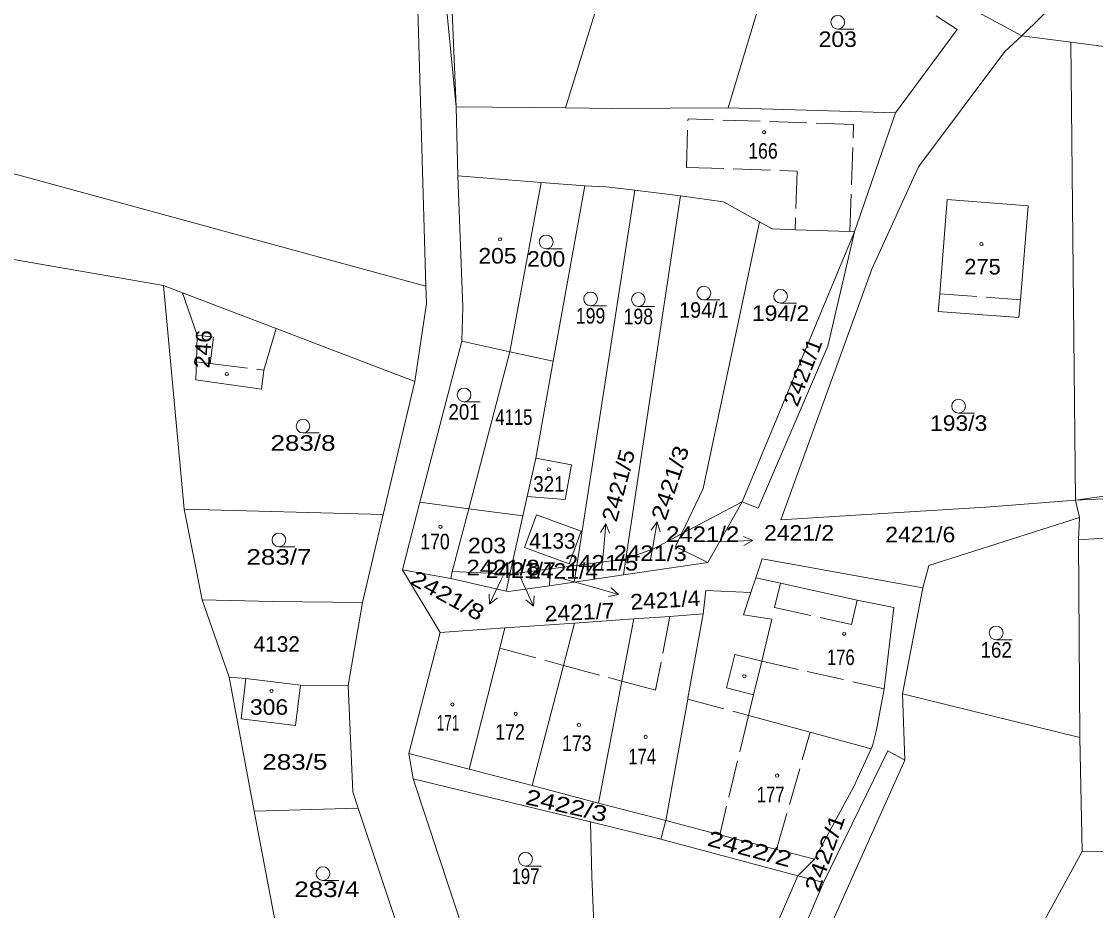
# Model space of a CAD drawing. Extents: x -590528 to -586543, y -1119609 to -1116685.
# Drawn here: x -589035.6 to -588918.3, y -1118218.9 to -1118121.8 of the extents above; entities that cross this region are included whole.
import ezdxf
from ezdxf.enums import TextEntityAlignment as Align

# ---------------------------------------------------------------- set-up
doc = ezdxf.new("R2010")
doc.units = 0
doc.header["$LTSCALE"] = 0.68
doc.linetypes.add('LONG_DASHED', pattern=[7.5, 6, -1.5])
for name, color, linetype, lineweight in [('1', 7, 'Continuous', 13), ('2', 7, 'LONG_DASHED', 13), ('3', 7, 'Continuous', 13), ('6', 7, 'Continuous', 13)]:
    doc.layers.add(name, color=color, linetype=linetype, lineweight=lineweight)

msp = doc.modelspace()

# ---------------------------------------------------------------- linework, layer by layer
at = {"layer": '1'}
for p, q in [((-588993.92, -1118065.79), (-588991.42, -1118150.69)), ((-588958.38, -1118131.22), (-588951.97, -1118109.75)), ((-588970.83, -1118113.91), (-588976.15, -1118131.23)), ((-588921.38, -1118118.49), (-588926.3, -1118123.37)), ((-588991.42, -1118150.69), (-589107.54, -1118119.06)), ((-588934.5, -1118118.92), (-588926.3, -1118123.37)), ((-588935.65, -1118121.17), (-588933.39, -1118122.65)), ((-588940.12, -1118131.78), (-588933.39, -1118122.65)), ((-588902.6, -1118126.42), (-588920.96, -1118124.06)), ((-588988.11, -1118131.1), (-588987.93, -1118138.66)), ((-588958.38, -1118131.22), (-588971.08, -1118131.29)), ((-588940.12, -1118131.78), (-588958.38, -1118131.22)), ((-588944.59, -1118144.75), (-588940.12, -1118131.78)), ((-588978.84, -1118139.38), (-588987.93, -1118138.66)), ((-588987.93, -1118138.66), (-588987.39, -1118153.01)), ((-588982.25, -1118157.86), (-588978.84, -1118139.38)), ((-588968.59, -1118140.23), (-588974.94, -1118181.22)), ((-588963.6, -1118140.83), (-588969.57, -1118180.5)), ((-588926.45, -1118152.2), (-588925.63, -1118141.93)), ((-588954.98, -1118143.67), (-588961.12, -1118172.82)), ((-588944.59, -1118144.75), (-588956.86, -1118174.25)), ((-588953.58, -1118144.44), (-588951.09, -1118144.53)), ((-588951.09, -1118144.53), (-588945.09, -1118144.73)), ((-588944.59, -1118144.75), (-588947.52, -1118157.25)), ((-588945.09, -1118144.73), (-588944.59, -1118144.75)), ((-589020.1, -1118150.63), (-589017.84, -1118175.07)), ((-588991.42, -1118150.69), (-588991.36, -1118152.59)), ((-589016.4, -1118156.04), (-589018.03, -1118151.42)), ((-588926.45, -1118152.2), (-588926.63, -1118154.13)), ((-588991.36, -1118152.59), (-588992.63, -1118161.11)), ((-588987.39, -1118153.01), (-588987.5, -1118156.69)), ((-589009.12, -1118159.87), (-589007.77, -1118155.33)), ((-588992.63, -1118161.11), (-589007.77, -1118155.33)), ((-588987.5, -1118156.69), (-588992.09, -1118174.29)), ((-588987.5, -1118156.69), (-588982.25, -1118157.86)), ((-588947.52, -1118157.25), (-588955.11, -1118174.96)), ((-588982.25, -1118157.86), (-588977.51, -1118158.9)), ((-589009.38, -1118161.96), (-589009.12, -1118159.87)), ((-589016.56, -1118160.95), (-589009.38, -1118161.96)), ((-588996.08, -1118175.63), (-588992.63, -1118161.11)), ((-588979.41, -1118169.5), (-588975.51, -1118170.21)), ((-588975.51, -1118170.21), (-588976.2, -1118174.01)), ((-588980.34, -1118173.66), (-588976.2, -1118174.01)), ((-588961.12, -1118172.82), (-588963.48, -1118177.76)), ((-588919.99, -1118175.98), (-588920.43, -1118174.06)), ((-589017.84, -1118175.07), (-588996.08, -1118175.63)), ((-589017.84, -1118175.07), (-589015.85, -1118184.98)), ((-588998.36, -1118185.26), (-588996.08, -1118175.63)), ((-588980.82, -1118175.8), (-588982.24, -1118182.15)), ((-588979.35, -1118175.67), (-588980.66, -1118179.24)), ((-588974.47, -1118177.46), (-588979.35, -1118175.67)), ((-588936.45, -1118181.22), (-588919.99, -1118175.98)), ((-588889.64, -1118176.31), (-588920.1, -1118178.41)), ((-588974.47, -1118177.46), (-588975.78, -1118181.03)), ((-588963.48, -1118177.76), (-588964.14, -1118179.15)), ((-588980.66, -1118179.24), (-588975.78, -1118181.03)), ((-588966.54, -1118179.39), (-588969.57, -1118180.5)), ((-588964.14, -1118179.15), (-588960.63, -1118180.9)), ((-588969.57, -1118180.5), (-588974.94, -1118181.22)), ((-588969.57, -1118180.5), (-588969.83, -1118182.24)), ((-588937.13, -1118183.65), (-588954.68, -1118180.5)), ((-588993.99, -1118181.68), (-588989.86, -1118188.53)), ((-588982.24, -1118182.15), (-588988.54, -1118181.86)), ((-588977.83, -1118181.59), (-588982.24, -1118182.15)), ((-588977.83, -1118181.59), (-588977.92, -1118183.42)), ((-588974.94, -1118181.22), (-588977.83, -1118181.59)), ((-588960.63, -1118180.9), (-588969.83, -1118182.24)), ((-588982.24, -1118182.15), (-588982.66, -1118184.01)), ((-588969.83, -1118182.24), (-588975.22, -1118183.03)), ((-588952.69, -1118183.15), (-588955.37, -1118182.56)), ((-588977.92, -1118183.42), (-588982.38, -1118184.07)), ((-588944.31, -1118184.99), (-588952.69, -1118183.15)), ((-589015.85, -1118184.98), (-589008.19, -1118185.14)), ((-589012.92, -1118193.43), (-589015.85, -1118184.98)), ((-589008.19, -1118185.14), (-588998.36, -1118185.26)), ((-588999.9, -1118194.31), (-588998.36, -1118185.26)), ((-588940.28, -1118185.8), (-588944.31, -1118184.99)), ((-588961.13, -1118186.48), (-588964.76, -1118186.77)), ((-588962.79, -1118195.7), (-588961.13, -1118186.48)), ((-588953.63, -1118187.08), (-588956.71, -1118186.59)), ((-588941.34, -1118194.68), (-588940.28, -1118185.8)), ((-588975.17, -1118187.5), (-588976.38, -1118192.12)), ((-588968.69, -1118187.05), (-588970.01, -1118193.85)), ((-588964.76, -1118186.77), (-588968.69, -1118187.05)), ((-588954.73, -1118191.66), (-588953.63, -1118187.08)), ((-588982.79, -1118188.03), (-588989.86, -1118188.53)), ((-588982.79, -1118188.03), (-588983.35, -1118190.23)), ((-588957.67, -1118190.93), (-588954.73, -1118191.66)), ((-588976.38, -1118192.12), (-588979.82, -1118205.26)), ((-589011.08, -1118193.54), (-589012.92, -1118193.43)), ((-589011.08, -1118193.54), (-589011.62, -1118197.97)), ((-589011.08, -1118193.54), (-589005.12, -1118194.27)), ((-589005.12, -1118194.27), (-589005.66, -1118198.7)), ((-589005.12, -1118194.27), (-588999.9, -1118194.31)), ((-588999.42, -1118205.92), (-588999.9, -1118194.31)), ((-588970.01, -1118193.85), (-588972.57, -1118207.16)), ((-588942.18, -1118199.18), (-588941.34, -1118194.68)), ((-588919.98, -1118200.01), (-588939.36, -1118195.25)), ((-589011.62, -1118197.97), (-589005.66, -1118198.7)), ((-588949.42, -1118199.43), (-588942.77, -1118201.23)), ((-588942.63, -1118200.92), (-588942.18, -1118199.18)), ((-588919.98, -1118200.01), (-588919.7, -1118212.47)), ((-588993.28, -1118201.74), (-588986.71, -1118203.46)), ((-588964.17, -1118258.31), (-588939.08, -1118202.48)), ((-588992.82, -1118204.5), (-588986.92, -1118222.32)), ((-588948.96, -1118213.3), (-588944.68, -1118205.37)), ((-588998.82, -1118207.72), (-588999.42, -1118205.92)), ((-589010.17, -1118208.04), (-588998.82, -1118207.72)), ((-588972.57, -1118207.16), (-588965.2, -1118209.08)), ((-588973.28, -1118215.23), (-588973.44, -1118209.23)), ((-588965.75, -1118211.1), (-588965.2, -1118209.08)), ((-588965.2, -1118209.08), (-588959.31, -1118210.62)), ((-588965.75, -1118211.1), (-588950.77, -1118215.1)), ((-588957.24, -1118211.17), (-588959.31, -1118210.62)), ((-588952.06, -1118212.5), (-588948.96, -1118213.3)), ((-588948.96, -1118213.3), (-588950.77, -1118215.1)), ((-588919.7, -1118212.47), (-588948.76, -1118265.18)), ((-588973.03, -1118221.16), (-588973.28, -1118215.23)), ((-588967.71, -1118253.93), (-588950.77, -1118215.1)), ((-588947.96, -1118215.85), (-588965.82, -1118257.59)), ((-588950.77, -1118215.1), (-588947.96, -1118215.85))]:
    msp.add_line(p, q, dxfattribs=at)
for points in [[(-588992.07, -1118090.31), (-588988.11, -1118131.1), (-588989.35, -1118101.59)], [(-589136.75, -1118118.6), (-589071.59, -1118141.72), (-589020.1, -1118150.63)], [(-588920.96, -1118124.06), (-588920.43, -1118174.06), (-588930.25, -1118174.85), (-588943.89, -1118175.68)], [(-588920.96, -1118124.06), (-588926.3, -1118123.37), (-588928.17, -1118125.08), (-588937.6, -1118137.68), (-588942.7, -1118148.83)], [(-588971.08, -1118131.29), (-588976.15, -1118131.23), (-588988.11, -1118131.1)], [(-588971.74, -1118139.85), (-588974.07, -1118139.74), (-588978.84, -1118139.38)], [(-588979.41, -1118169.5), (-588977.51, -1118158.9), (-588974.07, -1118139.74)], [(-588958.9, -1118141.49), (-588963.6, -1118140.83), (-588968.59, -1118140.23), (-588971.74, -1118139.85)], [(-588953.58, -1118144.44), (-588954.98, -1118143.67), (-588958.9, -1118141.49)], [(-588925.63, -1118141.93), (-588934.46, -1118141.24), (-588935.28, -1118151.52)], [(-588942.7, -1118148.83), (-588952.65, -1118176.23), (-588943.89, -1118175.68)], [(-589007.77, -1118155.33), (-589018.03, -1118151.42), (-589020.1, -1118150.63)], [(-588935.28, -1118151.52), (-588935.43, -1118153.45), (-588926.63, -1118154.13)], [(-589016.56, -1118160.95), (-589016.5, -1118158.95), (-589016.4, -1118156.04)], [(-588988.68, -1118182.63), (-588988.54, -1118181.86), (-588986.74, -1118175.01), (-588982.25, -1118157.86)], [(-588980.82, -1118175.8), (-588980.34, -1118173.66), (-588979.41, -1118169.5)], [(-588920.43, -1118174.06), (-588912.66, -1118173), (-588884.62, -1118169.19)], [(-588920.43, -1118174.06), (-588912.87, -1118173.7), (-588910.29, -1118173.25)], [(-588988.68, -1118182.63), (-588993.99, -1118181.68), (-588992.09, -1118174.29)], [(-588992.09, -1118174.29), (-588986.74, -1118175.01), (-588980.82, -1118175.8)], [(-588966.54, -1118179.39), (-588963.48, -1118177.76), (-588956.86, -1118174.25)], [(-588955.11, -1118174.96), (-588956.86, -1118174.25), (-588960.63, -1118180.9)], [(-588919.98, -1118200.01), (-588920.1, -1118178.41), (-588919.99, -1118175.98)], [(-588954.68, -1118180.5), (-588955.37, -1118182.56), (-588955.91, -1118184.18), (-588956.71, -1118186.59)], [(-588974.94, -1118181.22), (-588975.22, -1118183.03), (-588977.92, -1118183.42)], [(-588939.36, -1118195.25), (-588937.13, -1118183.65), (-588936.45, -1118181.22)], [(-588982.38, -1118184.07), (-588982.66, -1118184.01), (-588988.68, -1118182.63)], [(-588961.13, -1118186.48), (-588960.83, -1118183.95), (-588955.91, -1118184.18)], [(-588968.69, -1118187.05), (-588975.17, -1118187.5), (-588982.79, -1118188.03)], [(-588989.86, -1118188.53), (-588993.28, -1118201.74), (-588992.82, -1118204.5)], [(-588983.35, -1118190.23), (-588986.71, -1118203.46), (-588979.82, -1118205.26), (-588972.57, -1118207.16)], [(-588955.62, -1118195.35), (-588958.57, -1118194.57), (-588957.67, -1118190.93)], [(-589007.39, -1118222.8), (-589010.17, -1118208.04), (-589012.92, -1118193.43)], [(-588965.2, -1118209.08), (-588962.81, -1118195.8), (-588962.79, -1118195.7)], [(-588955.62, -1118195.35), (-588956.16, -1118197.6), (-588949.42, -1118199.43)], [(-588947.96, -1118215.85), (-588940.96, -1118201.47), (-588939.08, -1118202.48), (-588939.36, -1118195.25)], [(-588944.68, -1118205.37), (-588942.77, -1118201.23), (-588942.63, -1118200.92)], [(-588992.82, -1118204.5), (-588973.44, -1118209.23), (-588965.75, -1118211.1)], [(-588991.47, -1118229.81), (-588994.05, -1118222.05), (-588998.82, -1118207.72)], [(-588957.24, -1118211.17), (-588953.13, -1118212.23), (-588952.06, -1118212.5)], [(-588919.7, -1118212.47), (-588910.11, -1118212.57), (-588900.28, -1118212.67)]]:
    msp.add_lwpolyline(points, dxfattribs=at)
at = {"layer": '2'}
for p, q in [((-588962.96, -1118137.72), (-588962.78, -1118132.42)), ((-588944.69, -1118133.04), (-588962.78, -1118132.42)), ((-588945.09, -1118144.73), (-588944.69, -1118133.04)), ((-588962.96, -1118137.72), (-588950.87, -1118138.13)), ((-588950.87, -1118138.13), (-588951.09, -1118144.53)), ((-588935.28, -1118151.52), (-588926.45, -1118152.2)), ((-589016.4, -1118156.04), (-589014.62, -1118156.26)), ((-589014.62, -1118156.26), (-589014.98, -1118159.14)), ((-589016.5, -1118158.95), (-589014.98, -1118159.14)), ((-589014.98, -1118159.14), (-589009.12, -1118159.87)), ((-588953.33, -1118185.81), (-588952.69, -1118183.15)), ((-588944.31, -1118184.99), (-588944.9, -1118187.66)), ((-588953.33, -1118185.81), (-588944.9, -1118187.66)), ((-588964.76, -1118186.77), (-588966.33, -1118194.85)), ((-588954.73, -1118191.66), (-588955.62, -1118195.35)), ((-588954.73, -1118191.66), (-588941.34, -1118194.68)), ((-588970.01, -1118193.85), (-588966.33, -1118194.85)), ((-588962.81, -1118195.8), (-588956.16, -1118197.6)), ((-588956.16, -1118197.6), (-588959.31, -1118210.62)), ((-588953.13, -1118212.23), (-588949.42, -1118199.43))]:
    msp.add_line(p, q, dxfattribs=at)
msp.add_lwpolyline([(-588983.35, -1118190.23), (-588976.38, -1118192.12), (-588970.01, -1118193.85)], dxfattribs=at)
at = {"layer": '3'}
for p, q in [((-588971.748, -1118176.653), (-588972.03, -1118179.64)), ((-588966.141, -1118176.447), (-588966.67, -1118179.4)), ((-588966.91, -1118180.72), (-588966.67, -1118179.4)), ((-588961.18, -1118178.64), (-588958.71, -1118178.58)), ((-588955.711, -1118178.5), (-588958.71, -1118178.58)), ((-588972.23, -1118181.77), (-588972.03, -1118179.64)), ((-588984.469, -1118185.449), (-588983.2, -1118182.73)), ((-588982.99, -1118182.29), (-588983.2, -1118182.73)), ((-588981.05, -1118182.57), (-588980.89, -1118182.93)), ((-588979.649, -1118185.661), (-588980.89, -1118182.93)), ((-588976.43, -1118182.66), (-588973.26, -1118183.56)), ((-588970.372, -1118184.373), (-588973.26, -1118183.56))]:
    msp.add_line(p, q, dxfattribs=at)
for points in [[(-588972.339, -1118177.601), (-588971.748, -1118176.653), (-588971.343, -1118177.696)], [(-588966.809, -1118177.343), (-588966.141, -1118176.447), (-588965.824, -1118177.52)], [(-588956.723, -1118178.028), (-588955.711, -1118178.5), (-588956.698, -1118179.028)], [(-588971.199, -1118183.622), (-588970.372, -1118184.373), (-588971.471, -1118184.584)], [(-588983.594, -1118184.754), (-588984.469, -1118185.449), (-588984.5, -1118184.33)], [(-588979.608, -1118184.545), (-588979.649, -1118185.661), (-588980.519, -1118184.958)]]:
    msp.add_lwpolyline(points, dxfattribs=at)
at = {"layer": '6'}
for p, q in [((-588946.42, -1118122.62), (-588944.67, -1118122.62)), ((-588978.28, -1118146.62), (-588976.53, -1118146.62)), ((-588961.05, -1118152.2), (-588959.3, -1118152.2)), ((-588952.67, -1118152.55), (-588950.92, -1118152.55)), ((-588973.43, -1118152.84), (-588971.68, -1118152.84)), ((-588968.21, -1118152.91), (-588966.46, -1118152.91)), ((-588987.25, -1118163.33), (-588985.5, -1118163.33)), ((-588933.21, -1118164.56), (-588931.46, -1118164.56)), ((-589004.85, -1118166.73), (-589003.1, -1118166.73)), ((-589007.48, -1118179.17), (-589005.73, -1118179.17)), ((-588929.11, -1118189.33), (-588927.36, -1118189.33)), ((-588980.54, -1118214.06), (-588978.79, -1118214.06)), ((-589002.67, -1118215.62), (-589000.92, -1118215.62))]:
    msp.add_line(p, q, dxfattribs=at)
for centre, radius in [((-588946.42, -1118121.87), 0.75), ((-588954.4702, -1118133.8804), 0.175), ((-588983.3102, -1118145.5804), 0.175), ((-588978.28, -1118145.87), 0.75), ((-588930.7202, -1118146.1004), 0.175), ((-588973.43, -1118152.09), 0.75), ((-588961.05, -1118151.45), 0.75), ((-588952.67, -1118151.8), 0.75), ((-588968.21, -1118152.16), 0.75), ((-589016.2101, -1118157.5502), 0.1172), ((-589013.1702, -1118160.3004), 0.175), ((-588987.25, -1118162.58), 0.75), ((-588933.21, -1118163.81), 0.75), ((-589004.85, -1118165.98), 0.75), ((-588977.9802, -1118170.7104), 0.175), ((-588989.8302, -1118176.9804), 0.175), ((-589007.48, -1118178.42), 0.75), ((-588945.7202, -1118188.6704), 0.175), ((-588929.11, -1118188.58), 0.75), ((-588956.6202, -1118193.3204), 0.175), ((-589008.2902, -1118194.9204), 0.175), ((-588988.5302, -1118196.4004), 0.175), ((-588981.6102, -1118197.4104), 0.175), ((-588974.7002, -1118198.6304), 0.175), ((-588967.4102, -1118199.9404), 0.175), ((-588953.0502, -1118204.1604), 0.175), ((-588980.54, -1118213.31), 0.75), ((-589002.67, -1118214.87), 0.75)]:
    msp.add_circle(centre, radius, dxfattribs=at)

# ---------------------------------------------------------------- texts
at = {"layer": '3'}
for s, width, p in [('203', 1.1, (-588946.4205, -1118124.57)), ('166', 0.85, (-588954.59, -1118136.77)), ('205', 1.1, (-588983.6, -1118148.23)), ('200', 1.1, (-588978.28, -1118148.57)), ('275', 1.05, (-588930.601, -1118149.42)), ('194/1', 0.95, (-588961.05, -1118154.15)), ('199', 0.85, (-588973.43, -1118154.79)), ('198', 0.85, (-588968.21, -1118154.86)), ('194/2', 1.1, (-588952.6705, -1118154.5)), ('201', 0.9, (-588987.2505, -1118165.28)), ('4115', 0.8, (-588981.81, -1118165.85)), ('193/3', 1.1, (-588933.21, -1118166.51)), ('283/8', 1.25, (-589004.8505, -1118168.68)), ('321', 0.9, (-588977.9805, -1118173.15)), ('2421/2', 1.15, (-588961.181, -1118178.64)), ('2421/6', 1.1, (-588937.4005, -1118178.68)), ('170', 0.85, (-588990.4305, -1118179.45)), ('203', 1.1, (-588984.7405, -1118179.88)), ('283/7', 1.25, (-589007.48, -1118181.12)), ('2421/3', 1.15, (-588966.9095, -1118180.72)), ('2421/8', 1.15, (-588982.9905, -1118182.29)), ('2421/5', 1.15, (-588972.2295, -1118181.77)), ('2421/7', 1.1, (-588981.0505, -1118182.57)), ('2421/4', 1.1, (-588976.4315, -1118182.66)), ('162', 0.9, (-588929.1105, -1118191.28)), ('176', 0.8, (-588946.0805, -1118192.09)), ('306', 1.1, (-589008.5605, -1118197.52)), ('171', 0.65, (-588989.0005, -1118199.24)), ('172', 0.85, (-588982.2205, -1118200.25)), ('173', 0.85, (-588974.9305, -1118201.48)), ('283/5', 1.25, (-589005.74, -1118203.52)), ('174', 0.8, (-588967.7905, -1118202.94)), ('177', 0.8, (-588953.7505, -1118207.08)), ('197', 0.8, (-588980.5405, -1118216.01)), ('283/4', 1.25, (-589002.2505, -1118217.43))]:
    msp.add_text(s, height=1.7, dxfattribs=dict(at, width=width)).set_placement(p, align=Align.CENTER)
for s, rotation, width, p in [('246', 86.287, 1.1, (-589014.9361, -1118157.6255)), ('2421/1', 68.755, 1.1, (-588949.4404, -1118160.4035)), ('2422/3', 347.327, 1.3, (-588976.2445, -1118208.2618)), ('2422/1', 70.474, 1.25, (-588947.0399, -1118212.8956)), ('2422/2', 345.092, 1.35, (-588956.2712, -1118212.9885))]:
    msp.add_text(s, height=1.7, rotation=rotation, dxfattribs=dict(at, width=width)).set_placement(p, align=Align.CENTER)
for s, rotation, width, p in [('2421/5', 75.172, 1.15, (-588970.589, -1118176.541)), ('2421/3', 71.792, 1.2, (-588965.236, -1118176.414)), ('2421/4', 3.266, 1.1, (-588969.036, -1118186.054)), ('2421/7', 2.807, 1.1, (-588978.41, -1118187.346))]:
    msp.add_text(s, height=1.7, rotation=rotation, dxfattribs=dict(at, width=width)).set_placement(p)
at = {"layer": '3', "width": 1.1}
msp.add_text('2421/2', height=1.7, dxfattribs=at).set_placement((-588954.473, -1118178.5))
at = {"layer": '3'}
for s, p in [('4133', (-588977.6, -1118179.38)), ('4132', (-589007.72, -1118190.64))]:
    msp.add_text(s, height=1.7, dxfattribs=at).set_placement(p, align=Align.CENTER)
at = {"layer": '3', "width": 1.25}
msp.add_text('2421/8', height=1.7, rotation=331.399, dxfattribs=at).set_placement((-588985.6398, -1118187.3218), align=Align.RIGHT)

doc.saveas('drawing.dxf')
